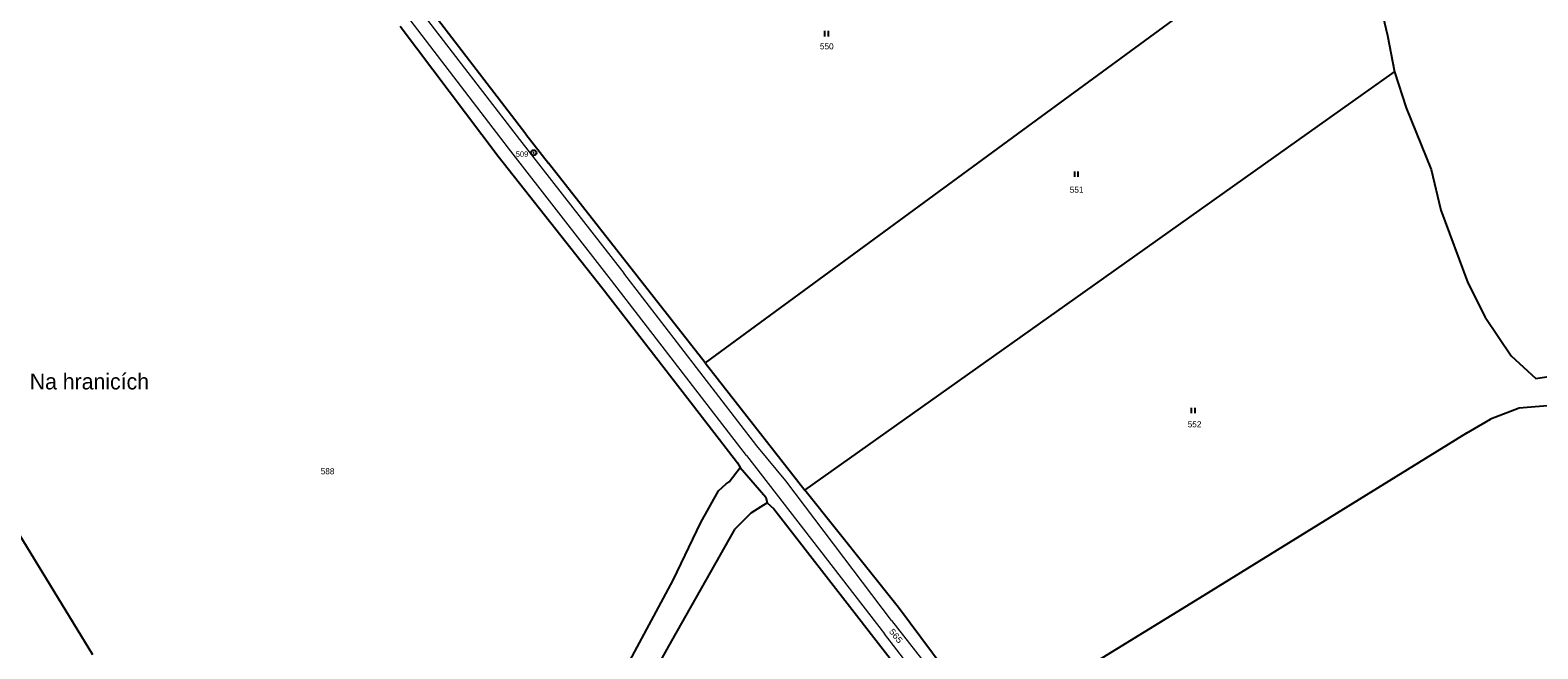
# Model space of a CAD drawing. Extents: x -653193 to -651624, y -1092017 to -1090260.
# Drawn here: x -652826.7 to -652409.3, y -1091598.3 to -1091426.8 of the extents above; entities that cross this region are included whole.
import ezdxf
from ezdxf.enums import TextEntityAlignment as Align

# ---------------------------------------------------------------- set-up
doc = ezdxf.new("R2010")
doc.units = 0
doc.header["$LTSCALE"] = 0.68
for name, color, linetype, lineweight in [('1', 7, 'Continuous', 25), ('3', 7, 'Continuous', 25), ('4', 7, 'Continuous', 13), ('7', 7, 'Continuous', 13), ('8', 7, 'Continuous', 25)]:
    doc.layers.add(name, color=color, linetype=linetype, lineweight=lineweight)
doc.layers.add('2', color=7, linetype='Continuous')

msp = doc.modelspace()

# ---------------------------------------------------------------- linework, layer by layer
at = {"layer": '1'}
for p, q in [((-652461.12, -1091387.85), (-652551.95, -1091454.53)), ((-652689.47, -1091455.61), (-652725.9, -1091408.1)), ((-652455.08, -1091410.25), (-652450.86, -1091428.27)), ((-652724.32, -1091425.66), (-652697.11, -1091461.71)), ((-652450.86, -1091428.27), (-652448.93, -1091438.32)), ((-652532.32, -1091497.57), (-652448.93, -1091438.32)), ((-652448.93, -1091438.32), (-652445.69, -1091448.31)), ((-652445.69, -1091448.31), (-652438.75, -1091465.43)), ((-652689.47, -1091455.61), (-652683.2, -1091463.62)), ((-652551.95, -1091454.53), (-652639.82, -1091519.03)), ((-652697.11, -1091461.71), (-652668.32, -1091498.17)), ((-652639.82, -1091519.03), (-652683.2, -1091463.62)), ((-652438.75, -1091465.43), (-652436.1, -1091476.68)), ((-652436.1, -1091476.68), (-652428.66, -1091496.86)), ((-652428.66, -1091496.86), (-652423.84, -1091506.32)), ((-652668.32, -1091498.17), (-652644.66, -1091528.85)), ((-652612.2, -1091554.32), (-652532.32, -1091497.57)), ((-652423.84, -1091506.32), (-652416.67, -1091517.03)), ((-652416.67, -1091517.03), (-652409.8, -1091523.38)), ((-652639.82, -1091519.03), (-652612.2, -1091554.32)), ((-652409.8, -1091523.38), (-652397.91, -1091521.47)), ((-652644.66, -1091528.85), (-652630.9, -1091546.76)), ((-652404.4, -1091530.77), (-652414.4, -1091531.54)), ((-652429.01, -1091538.54), (-652422.34, -1091534.58)), ((-652414.4, -1091531.54), (-652422.34, -1091534.58)), ((-652429.01, -1091538.54), (-652502.91, -1091584.25)), ((-652630.9, -1091546.76), (-652630.16, -1091548)), ((-652633.2, -1091552.03), (-652630.16, -1091548)), ((-652630.16, -1091548), (-652623, -1091556.22)), ((-652641.06, -1091563.31), (-652636.17, -1091554.47)), ((-652636.17, -1091554.47), (-652634.05, -1091552.51)), ((-652634.05, -1091552.51), (-652633.2, -1091552.03)), ((-652586.29, -1091586.79), (-652612.2, -1091554.32)), ((-652809.38, -1091599.93), (-652836.23, -1091556.01)), ((-652622.62, -1091557.85), (-652627.14, -1091560.67)), ((-652623, -1091556.22), (-652622.62, -1091557.85)), ((-652622.62, -1091557.85), (-652620.84, -1091559.51)), ((-652620.84, -1091559.51), (-652587.97, -1091601.84)), ((-652648.66, -1091579.28), (-652641.06, -1091563.31)), ((-652627.14, -1091560.67), (-652631.67, -1091565.25)), ((-652631.67, -1091565.25), (-652649.19, -1091596.08)), ((-652664.65, -1091608.9), (-652648.66, -1091579.28)), ((-652502.91, -1091584.25), (-652561.46, -1091620.18)), ((-652561.46, -1091620.18), (-652586.29, -1091586.79)), ((-652649.19, -1091596.08), (-652671.5, -1091636.35))]:
    msp.add_line(p, q, dxfattribs=at)
at = {"layer": '3'}
for p, q in [((-652606.701, -1091428.5), (-652606.701, -1091427)), ((-652605.7, -1091428.5), (-652605.7, -1091427)), ((-652537.511, -1091467.46), (-652537.511, -1091465.96)), ((-652536.51, -1091467.46), (-652536.51, -1091465.96)), ((-652505.181, -1091532.94), (-652505.181, -1091531.44)), ((-652504.18, -1091532.94), (-652504.18, -1091531.44))]:
    msp.add_line(p, q, dxfattribs=at)
at = {"layer": '4'}
for p, q in [((-652718.25, -1091421.99), (-652691.2, -1091457.11)), ((-652694.28, -1091459.48), (-652721.52, -1091423.91)), ((-652665.77, -1091496.16), (-652694.28, -1091459.48)), ((-652691.2, -1091457.11), (-652662.39, -1091494.13)), ((-652628.41, -1091544.72), (-652665.77, -1091496.16)), ((-652625.49, -1091542.01), (-652662.39, -1091494.13)), ((-652617.5, -1091551.75), (-652625.49, -1091542.01)), ((-652628.41, -1091544.72), (-652590.18, -1091594.17)), ((-652588.22, -1091590.44), (-652617.5, -1091551.75)), ((-652588.22, -1091590.44), (-652548.06, -1091641.81)), ((-652555.93, -1091638.33), (-652590.18, -1091594.17))]:
    msp.add_line(p, q, dxfattribs=at)
at = {"layer": '8'}
for radius in [0.75, 0.03]:
    msp.add_circle((-652687.32, -1091460.7798), radius, dxfattribs=at)

# ---------------------------------------------------------------- texts
at = {"layer": '2'}
for s, p in [('550', (-652606.159, -1091432.095)), ('551', (-652536.969, -1091471.855)), ('552', (-652504.319, -1091536.885)), ('588', (-652744.389, -1091549.905))]:
    msp.add_text(s, height=1.7, dxfattribs=at).set_placement(p, align=Align.CENTER)
at = {"layer": '2', "width": 1.15}
msp.add_text('565', height=1.7, rotation=309, dxfattribs=at).set_placement((-652587.6593, -1091595.2491), align=Align.CENTER)
at = {"layer": '7'}
msp.add_text('Na hranicích', height=4.4, dxfattribs=at).set_placement((-652810.35, -1091526.38), align=Align.CENTER)
at = {"layer": '8'}
msp.add_text('509', height=1.5, dxfattribs=at).set_placement((-652688.819, -1091461.897), align=Align.RIGHT)

doc.saveas('drawing.dxf')
